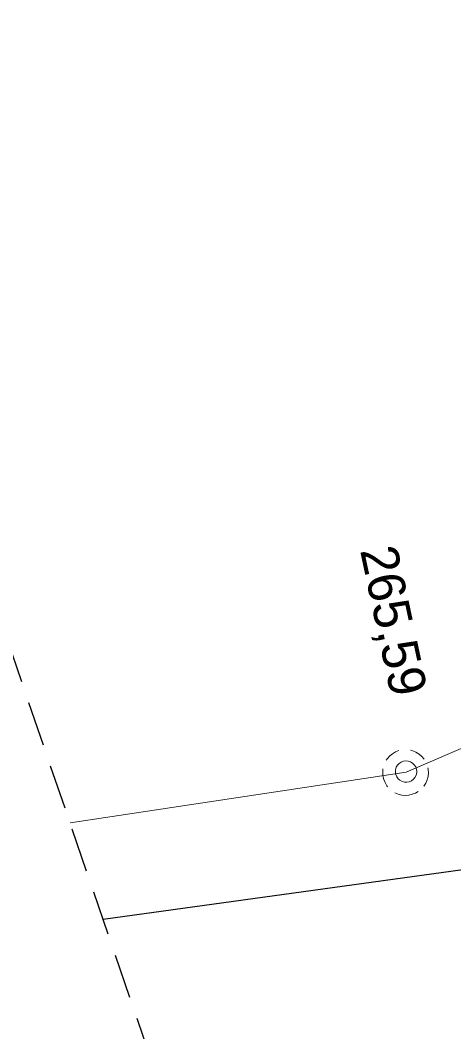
# Model space of a CAD drawing. Extents: x -732074 to -731966, y -1048695 to -1047982.
# Drawn here: x -732028.04 to -732018.68, y -1048554.48 to -1048532.64 of the extents above; entities that cross this region are included whole.
import ezdxf

# ---------------------------------------------------------------- set-up
doc = ezdxf.new("R2010")
doc.units = 0
doc.header["$LTSCALE"] = 0.32
doc.linetypes.add('MEDIUM_DASHED', pattern=[4.5, 3, -1.5])
doc.layers.add('1', color=7, linetype='Continuous')
for name, color, linetype, lineweight in [('18', 7, 'Continuous', 13), ('20', 7, 'Continuous', 13), ('63', 7, 'MEDIUM_DASHED', 25), ('8', 7, 'Continuous', 13)]:
    doc.layers.add(name, color=color, linetype=linetype, lineweight=lineweight)

msp = doc.modelspace()

# ---------------------------------------------------------------- linework, layer by layer
at = {"layer": '18'}
for points in [[(-732019.863, -1048548.407), (-732019.934, -1048548.435), (-732020, -1048548.474), (-732020.061, -1048548.522), (-732020.112, -1048548.579), (-732020.136, -1048548.613)], [(-732019.321, -1048548.59), (-732019.372, -1048548.532), (-732019.429, -1048548.482), (-732019.495, -1048548.441), (-732019.566, -1048548.412), (-732019.615, -1048548.398)], [(-732020.208, -1048548.799), (-732020.213, -1048548.876), (-732020.208, -1048548.953), (-732020.191, -1048549.028), (-732020.163, -1048549.099), (-732020.122, -1048549.165), (-732020.107, -1048549.187)], [(-732019.326, -1048549.176), (-732019.286, -1048549.111), (-732019.255, -1048549.041), (-732019.235, -1048548.966), (-732019.228, -1048548.89), (-732019.233, -1048548.813), (-732019.239, -1048548.778)], [(-732019.95, -1048549.316), (-732019.88, -1048549.347), (-732019.804, -1048549.366), (-732019.728, -1048549.373), (-732019.652, -1048549.368), (-732019.576, -1048549.351), (-732019.505, -1048549.323), (-732019.445, -1048549.288)]]:
    msp.add_lwpolyline(points, dxfattribs=at)
msp.add_lwpolyline([(-732019.478, -1048548.859), (-732019.485, -1048548.807), (-732019.502, -1048548.757), (-732019.531, -1048548.713), (-732019.569, -1048548.676), (-732019.614, -1048548.649), (-732019.664, -1048548.633), (-732019.716, -1048548.628), (-732019.767, -1048548.635), (-732019.816, -1048548.654), (-732019.86, -1048548.684), (-732019.896, -1048548.723), (-732019.922, -1048548.768), (-732019.936, -1048548.819), (-732019.94, -1048548.871), (-732019.931, -1048548.923), (-732019.911, -1048548.971), (-732019.88, -1048549.014), (-732019.841, -1048549.049), (-732019.794, -1048549.073), (-732019.744, -1048549.087), (-732019.691, -1048549.089), (-732019.64, -1048549.079), (-732019.592, -1048549.057), (-732019.549, -1048549.025), (-732019.517, -1048548.985), (-732019.493, -1048548.938), (-732019.48, -1048548.887)], close=True, dxfattribs=at)
at = {"layer": '20'}
msp.add_line((-732026.963, -1048549.969), (-732019.71, -1048548.87), dxfattribs=at)
msp.add_line((-732026.963, -1048549.969), (-732019.71, -1048548.87), dxfattribs=at)
msp.add_lwpolyline([(-732019.71, -1048548.87), (-732017.166, -1048547.78), (-732006.969, -1048543.29)], dxfattribs=at)
msp.add_lwpolyline([(-732019.71, -1048548.87), (-732017.166, -1048547.78), (-732006.969, -1048543.29)], dxfattribs=at)
at = {"layer": '63'}
msp.add_lwpolyline([(-731995.365, -1048690.893), (-731995.541, -1048612.001), (-732022.871, -1048561.911), (-732022.871, -1048561.909), (-732073.995, -1048412.717)], dxfattribs=at)
at = {"layer": '8', "lineweight": 25}
msp.add_lwpolyline([(-732008.149, -1048549.18), (-732009.997, -1048549.686), (-732015.672, -1048550.592), (-732026.249, -1048552.052)], dxfattribs=at)

# ---------------------------------------------------------------- texts
at = {"layer": '1'}
for p in [(-732020.704, -1048544.082), (-732020.704, -1048544.083)]:
    msp.add_text('265,59', height=0.8, rotation=282, dxfattribs=at).set_placement(p)

doc.saveas('drawing.dxf')
